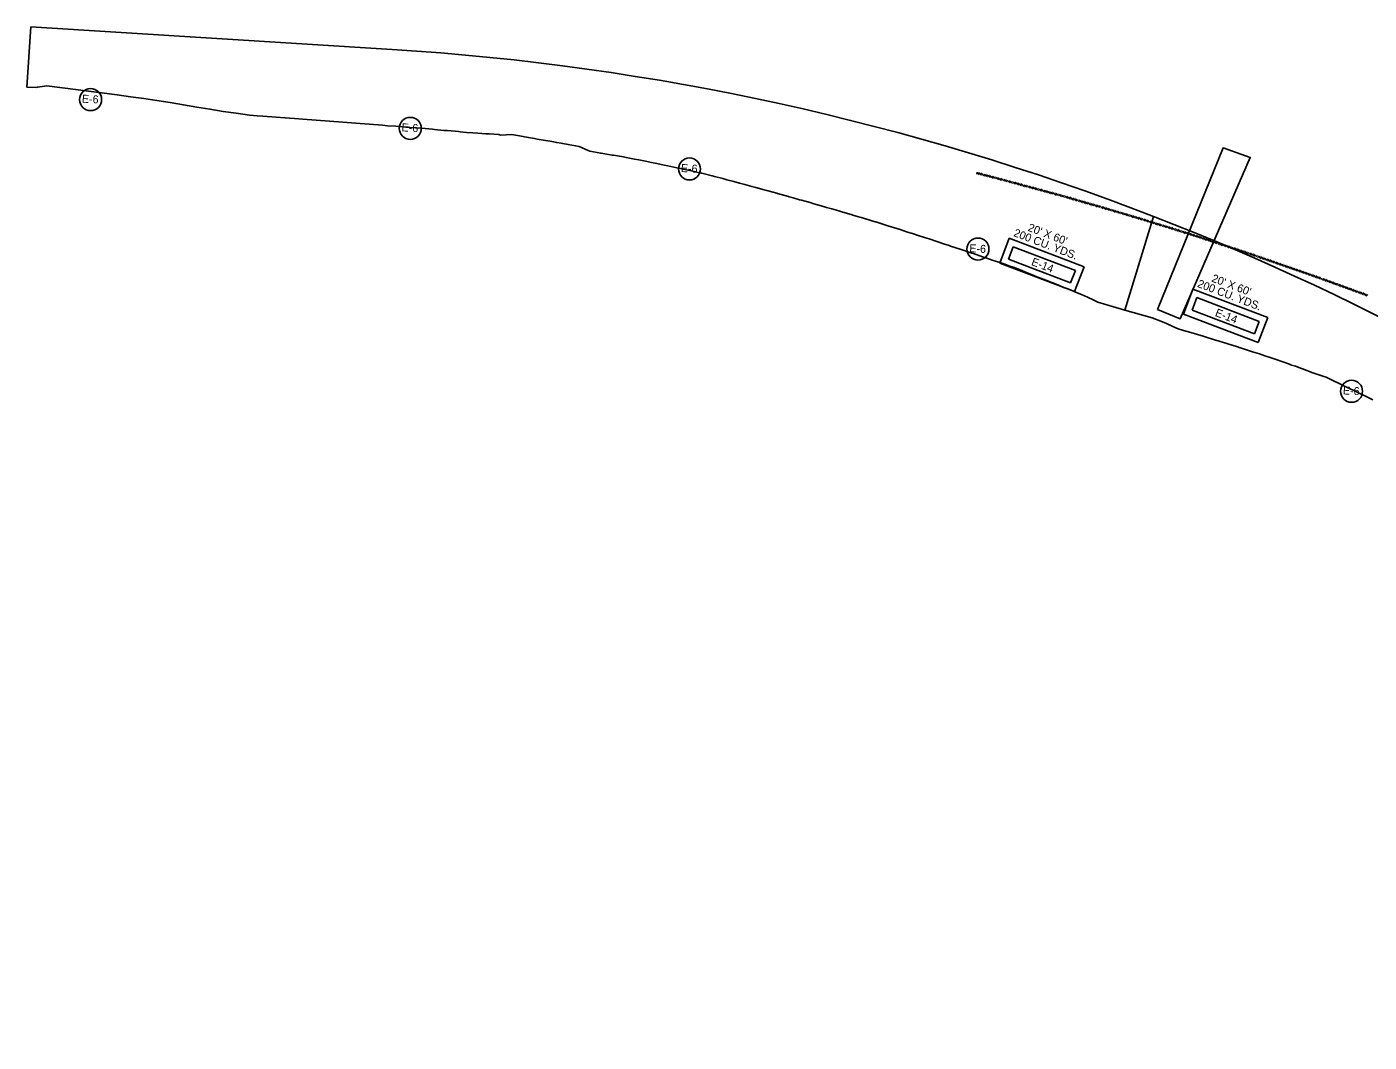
# Model space of a CAD drawing. Extents: x 881727 to 890277, y 1562105 to 1567179.
# Drawn here: x 881727 to 882733, y 1566418 to 1567179 of the extents above; entities that cross this region are included whole.
import ezdxf

# ---------------------------------------------------------------- set-up
doc = ezdxf.new("R2010")
doc.units = 0
for name, color, linetype in [('22', 7, 'Continuous'), ('R_Axis', 7, 'Continuous'), ('R_Water', 7, 'Continuous')]:
    doc.layers.add(name, color=color, linetype=linetype)

msp = doc.modelspace()

# ---------------------------------------------------------------- linework, layer by layer
at = {"layer": '22'}
for p, q in [((881729.8, 1567178.9), (881726.9, 1567133.7)), ((882000.8, 1567162), (881729.8, 1567178.9)), ((882550.2, 1566966.6), (882571.8, 1567036.8)), ((882550.2, 1566966.6), (882571.8, 1567036.8)), ((882550.2, 1566966.6), (882550.2, 1566966.6)), ((882550.3, 1566966.6), (882550.2, 1566966.6))]:
    msp.add_line(p, q, dxfattribs=at)
for points in [[(881726.9, 1567133.7), (881733.8, 1567133.4), (881734.9, 1567133.7), (881741.8, 1567134.7)], [(881741.8, 1567134.7), (881784.8, 1567129.2), (881794.7, 1567127.9), (881804.6, 1567126.5), (881814.6, 1567125.3), (881824.5, 1567123.7), (881834.4, 1567122.1), (881844.3, 1567120.4), (881854.3, 1567118.8), (881864.2, 1567117.2), (881874.1, 1567115.5), (881884, 1567114.1), (881894, 1567112.8), (881899.6, 1567112.3), (881903.9, 1567112), (881913.9, 1567111.2), (881923.9, 1567110.4), (881927.7, 1567110.1), (881933.8, 1567109.6), (881943.8, 1567108.9), (881953.8, 1567108.1), (881963.8, 1567107.4), (881973.7, 1567106.6), (881983.7, 1567105.9), (881993.7, 1567105.1), (881997.3, 1567104.8), (882003.5, 1567104.4), (882005.8, 1567104.2), (882011.1, 1567103.8), (882013.1, 1567103.6), (882014.2, 1567103.5), (882022.7, 1567102.9), (882022.8, 1567102.9), (882031.2, 1567102.1), (882032.5, 1567102), (882039.7, 1567101.3), (882042.1, 1567101.2), (882048.2, 1567100.7), (882050.5, 1567100.5), (882051.8, 1567100.3), (882056.6, 1567099.8), (882061.4, 1567099.4), (882065.1, 1567099.1), (882071.1, 1567098.7), (882073.6, 1567098.6), (882080.8, 1567098.1), (882082.1, 1567097.8), (882090.6, 1567098.1), (882090.7, 1567098.1), (882099.1, 1567096.6), (882100.1, 1567096.4), (882107.5, 1567095.2), (882109.7, 1567094.8), (882115.9, 1567093.7), (882119.3, 1567093.1), (882124.3, 1567092.2), (882127.5, 1567091.7), (882128.8, 1567091.4), (882132.7, 1567090.8), (882138.4, 1567089.8), (882141, 1567089.3), (882147.7, 1567086.3), (882149.1, 1567085.7), (882157.2, 1567084.2), (882157.5, 1567084.2), (882165.9, 1567082.8), (882166.7, 1567082.7), (882174.2, 1567081.4), (882176.3, 1567081), (882182.6, 1567079.8), (882185.8, 1567079.2), (882190.9, 1567078.2), (882195.3, 1567077.3), (882199.2, 1567076.5), (882204.8, 1567075.3), (882207.6, 1567074.7), (882214.2, 1567073.3), (882215.9, 1567073), (882223.7, 1567071.3), (882224.2, 1567071.2), (882232.4, 1567069.3), (882233.1, 1567069.1), (882240.7, 1567067.2), (882242.5, 1567066.7), (882248.9, 1567065.1), (882251.9, 1567064.3), (882257.1, 1567062.9), (882261.2, 1567061.8), (882265.3, 1567060.7), (882270.6, 1567059.3), (882273.5, 1567058.5), (882279.9, 1567056.7), (882281.7, 1567056.2), (882289.2, 1567054.1), (882289.9, 1567053.9), (882298, 1567051.6), (882298.5, 1567051.4), (882301.6, 1567050.6), (882306.2, 1567049.3), (882307.8, 1567048.9), (882314.3, 1567047.1), (882317.1, 1567046.3), (882322.5, 1567044.8), (882326.4, 1567043.6), (882330.6, 1567042.4), (882335.7, 1567041), (882338.8, 1567040.1), (882344.9, 1567038.2), (882346.9, 1567037.6), (882354.2, 1567035.5), (882355, 1567035.2), (882363.1, 1567032.8), (882363.4, 1567032.7), (882371.1, 1567030.2), (882372.6, 1567029.8), (882379.2, 1567027.7), (882381.8, 1567026.9), (882387.3, 1567025.1), (882391, 1567023.9), (882395.3, 1567022.5), (882400.1, 1567020.9), (882403.4, 1567019.9), (882409.3, 1567018), (882411.4, 1567017.3), (882414.2, 1567016.3), (882418.4, 1567014.9), (882419.4, 1567014.6), (882427.5, 1567012), (882427.6, 1567011.9), (882435.5, 1567009.3), (882436.7, 1567008.9), (882443.5, 1567006.6), (882445.9, 1567005.8), (882451.5, 1567003.8), (882455, 1567002.7), (882459.5, 1567001.2), (882464.1, 1566999.6), (882467.4, 1566998.4), (882473.1, 1566996.2), (882475.3, 1566995.3), (882480.2, 1566993.3), (882482, 1566992.6), (882483.1, 1566992.1), (882491, 1566989.1), (882491, 1566989.1), (882498.8, 1566985.9), (882499.9, 1566985.4), (882504.3, 1566983.6), (882506.7, 1566982.7), (882508.8, 1566981.9), (882514.5, 1566979.6), (882517.7, 1566978.2), (882522.3, 1566976.2), (882526.5, 1566974.3), (882529.9, 1566972.5), (882550.2, 1566966.6)], [(882570.7, 1566960.7), (882550.3, 1566966.6)], [(882736.1, 1566899.3), (882730.2, 1566902.2), (882727.4, 1566903.6), (882722.5, 1566906), (882718.6, 1566907.8), (882714.9, 1566909.6), (882709.9, 1566912), (882707.2, 1566913.3), (882701.1, 1566916.2), (882699.4, 1566916.8), (882691.9, 1566919.4), (882691.3, 1566919.6), (882683.4, 1566922.6), (882682.8, 1566922.8), (882678.2, 1566924.5), (882675.3, 1566925.4), (882673.6, 1566926), (882669.5, 1566927.5), (882667.3, 1566928.3), (882664.5, 1566929.3), (882659.2, 1566931.1), (882655.2, 1566932.3), (882651.1, 1566933.7), (882645.9, 1566935.3), (882642.9, 1566936.3), (882636.9, 1566938.3), (882636.7, 1566938.3), (882634.8, 1566938.9), (882627.4, 1566941.2), (882626.7, 1566941.4), (882618.5, 1566944), (882618.2, 1566944.1), (882610.4, 1566946.4), (882608.9, 1566946.9), (882602.3, 1566948.9), (882599.6, 1566949.7), (882594.1, 1566951.3), (882590.3, 1566952.5), (882586.2, 1566954.3), (882581.5, 1566956.4), (882578.5, 1566957.7), (882570.7, 1566960.7)]]:
    msp.add_lwpolyline(points, dxfattribs=at)
msp.add_lwpolyline([(882574.6, 1566967), (882623.9, 1567088.1), (882644.2, 1567081), (882591.8, 1566960.1)], close=True, dxfattribs=at)
for start, end in [(68.8256, 86.4305), (37.4722, 68.8256)]:
    msp.add_arc((881881.9, 1565255.8), 1909.9, start, end, dxfattribs=at)
at = {"layer": 'R_Water'}
for p, q in [((882439.2, 1567068.5), (882439.6, 1567069.9)), ((882439.2, 1567068.5), (882440.5, 1567069.7)), ((882440.3, 1567068.2), (882441.7, 1567069.4)), ((882441.5, 1567067.9), (882442.9, 1567069.1)), ((882442.7, 1567067.6), (882444, 1567068.8)), ((882443.9, 1567067.3), (882445.2, 1567068.5)), ((882445, 1567067), (882446.4, 1567068.2)), ((882446.2, 1567066.7), (882447.5, 1567067.9)), ((882447.3, 1567066.4), (882448.7, 1567067.6)), ((882448.5, 1567066.1), (882449.9, 1567067.3)), ((882449.7, 1567065.8), (882451, 1567067)), ((882450.8, 1567065.5), (882452.2, 1567066.7)), ((882452, 1567065.2), (882453.3, 1567066.4)), ((882453.2, 1567064.9), (882454.5, 1567066.1)), ((882454.3, 1567064.6), (882455.7, 1567065.8)), ((882455.5, 1567064.3), (882456.8, 1567065.5)), ((882456.6, 1567064), (882458, 1567065.2)), ((882457.8, 1567063.7), (882459.1, 1567064.9)), ((882459, 1567063.4), (882460.3, 1567064.6)), ((882460.1, 1567063.1), (882461.5, 1567064.3)), ((882461.3, 1567062.8), (882462.6, 1567064)), ((882462.4, 1567062.5), (882463.8, 1567063.7)), ((882463.6, 1567062.1), (882464.9, 1567063.3)), ((882464.7, 1567061.8), (882466.1, 1567063)), ((882465.9, 1567061.5), (882467.2, 1567062.7)), ((882467, 1567061.2), (882468.4, 1567062.4)), ((882468.2, 1567060.9), (882469.5, 1567062.1)), ((882469.3, 1567060.6), (882470.7, 1567061.8)), ((882470.5, 1567060.3), (882471.8, 1567061.5)), ((882471.6, 1567060), (882473, 1567061.2)), ((882472.8, 1567059.7), (882474.1, 1567060.8)), ((882473.9, 1567059.3), (882475.3, 1567060.5)), ((882475.1, 1567059), (882476.4, 1567060.2)), ((882476.2, 1567058.7), (882477.6, 1567059.9)), ((882477.4, 1567058.4), (882478.7, 1567059.6)), ((882478.5, 1567058.1), (882479.9, 1567059.3)), ((882479.7, 1567057.8), (882481, 1567059)), ((882480.8, 1567057.5), (882482.2, 1567058.7)), ((882482, 1567057.2), (882483.3, 1567058.4)), ((882483.1, 1567056.9), (882484.5, 1567058)), ((882484.3, 1567056.5), (882485.6, 1567057.7)), ((882485.4, 1567056.2), (882486.8, 1567057.4)), ((882486.6, 1567055.9), (882487.9, 1567057.1)), ((882487.7, 1567055.6), (882489.1, 1567056.8)), ((882488.9, 1567055.3), (882490.2, 1567056.5)), ((882490, 1567055), (882491.4, 1567056.2)), ((882491.2, 1567054.7), (882492.5, 1567055.9)), ((882492.3, 1567054.4), (882493.7, 1567055.5)), ((882493.5, 1567054), (882494.8, 1567055.2)), ((882494.6, 1567053.7), (882496, 1567054.9)), ((882495.8, 1567053.4), (882497.1, 1567054.6)), ((882496.9, 1567053.1), (882498.3, 1567054.3)), ((882498.1, 1567052.8), (882499.4, 1567054)), ((882499.2, 1567052.5), (882500.6, 1567053.7)), ((882500.4, 1567052.2), (882501.7, 1567053.4)), ((882501.5, 1567051.9), (882502.8, 1567053)), ((882502.7, 1567051.5), (882504, 1567052.7)), ((882503.8, 1567051.2), (882505.1, 1567052.4)), ((882504.9, 1567050.9), (882506.2, 1567052.1)), ((882506.1, 1567050.6), (882507.4, 1567051.7)), ((882507.2, 1567050.2), (882508.5, 1567051.4)), ((882508.3, 1567049.9), (882509.7, 1567051.1)), ((882509.5, 1567049.6), (882510.8, 1567050.8)), ((882510.6, 1567049.3), (882511.9, 1567050.4)), ((882511.7, 1567048.9), (882513.1, 1567050.1)), ((882512.9, 1567048.6), (882514.2, 1567049.8)), ((882514, 1567048.3), (882515.3, 1567049.5)), ((882515.1, 1567047.9), (882516.5, 1567049.1)), ((882516.3, 1567047.6), (882517.6, 1567048.8)), ((882517.4, 1567047.3), (882518.7, 1567048.5)), ((882518.5, 1567047), (882519.9, 1567048.1)), ((882519.7, 1567046.6), (882521, 1567047.8)), ((882520.8, 1567046.3), (882522.1, 1567047.5)), ((882521.9, 1567046), (882523.3, 1567047.2)), ((882523.1, 1567045.7), (882524.4, 1567046.8)), ((882524.2, 1567045.3), (882525.5, 1567046.5)), ((882525.3, 1567045), (882526.7, 1567046.2)), ((882526.5, 1567044.7), (882527.8, 1567045.9)), ((882527.6, 1567044.4), (882528.9, 1567045.5)), ((882528.7, 1567044), (882530.1, 1567045.2)), ((882529.9, 1567043.7), (882531.2, 1567044.9)), ((882531, 1567043.4), (882532.3, 1567044.6)), ((882532.1, 1567043), (882533.5, 1567044.2)), ((882533.3, 1567042.7), (882534.6, 1567043.9)), ((882534.4, 1567042.4), (882535.7, 1567043.6)), ((882535.5, 1567042.1), (882536.9, 1567043.3)), ((882536.7, 1567041.7), (882538, 1567042.9)), ((882537.8, 1567041.4), (882539.1, 1567042.6)), ((882538.9, 1567041.1), (882540.3, 1567042.3)), ((882540.1, 1567040.8), (882541.4, 1567041.9)), ((882541.2, 1567040.4), (882542.5, 1567041.6)), ((882542.3, 1567040.1), (882543.7, 1567041.3)), ((882543.5, 1567039.8), (882544.8, 1567041)), ((882544.6, 1567039.5), (882545.9, 1567040.6)), ((882545.7, 1567039.1), (882547, 1567040.3)), ((882546.9, 1567038.8), (882548.2, 1567040)), ((882548, 1567038.4), (882549.3, 1567039.6)), ((882549.1, 1567038.1), (882550.4, 1567039.3)), ((882550.2, 1567037.8), (882551.5, 1567038.9)), ((882551.3, 1567037.4), (882552.6, 1567038.6)), ((882552.5, 1567037.1), (882553.8, 1567038.3)), ((882553.6, 1567036.8), (882554.9, 1567037.9)), ((882554.7, 1567036.4), (882556, 1567037.6)), ((882555.8, 1567036.1), (882557.1, 1567037.3)), ((882556.9, 1567035.7), (882558.3, 1567036.9)), ((882558.1, 1567035.4), (882559.4, 1567036.6)), ((882559.2, 1567035.1), (882560.5, 1567036.2)), ((882560.3, 1567034.7), (882561.6, 1567035.9)), ((882561.4, 1567034.4), (882562.7, 1567035.5)), ((882562.5, 1567034), (882563.8, 1567035.2)), ((882563.6, 1567033.7), (882565, 1567034.9)), ((882564.8, 1567033.4), (882566.1, 1567034.5)), ((882565.9, 1567033), (882567.2, 1567034.2)), ((882567, 1567032.7), (882568.3, 1567033.8)), ((882568.1, 1567032.3), (882569.4, 1567033.5)), ((882569.2, 1567032), (882570.5, 1567033.1)), ((882570.3, 1567031.6), (882571.6, 1567032.8)), ((882571.5, 1567031.3), (882572.8, 1567032.5)), ((882572.6, 1567031), (882573.9, 1567032.1)), ((882573.7, 1567030.6), (882575, 1567031.8)), ((882574.8, 1567030.3), (882576.1, 1567031.4)), ((882575.9, 1567029.9), (882577.2, 1567031.1)), ((882577, 1567029.6), (882578.3, 1567030.7)), ((882578.2, 1567029.2), (882579.5, 1567030.4)), ((882579.3, 1567028.9), (882580.6, 1567030.1)), ((882456.4, 1567001.8), (882463.5, 1567020.5)), ((882463.5, 1567020.5), (882519.6, 1566999.1)), ((882580.4, 1567028.6), (882581.7, 1567029.7)), ((882581.5, 1567028.2), (882582.8, 1567029.4)), ((882582.6, 1567027.9), (882583.9, 1567029)), ((882583.7, 1567027.5), (882585, 1567028.7)), ((882584.8, 1567027.2), (882586.1, 1567028.4)), ((882586, 1567026.8), (882587.3, 1567028)), ((882587.1, 1567026.5), (882588.4, 1567027.7)), ((882588.2, 1567026.1), (882589.5, 1567027.3)), ((882589.3, 1567025.8), (882590.6, 1567027)), ((882590.4, 1567025.5), (882591.7, 1567026.6)), ((882591.5, 1567025.1), (882592.8, 1567026.3)), ((882592.6, 1567024.8), (882593.9, 1567025.9)), ((882593.7, 1567024.4), (882595, 1567025.6)), ((882594.8, 1567024.1), (882596.1, 1567025.2)), ((882595.9, 1567023.7), (882597.2, 1567024.9)), ((882597.1, 1567023.4), (882598.4, 1567024.5)), ((882598.2, 1567023), (882599.5, 1567024.2)), ((882599.3, 1567022.7), (882600.6, 1567023.8)), ((882600.4, 1567022.3), (882601.7, 1567023.5)), ((882601.5, 1567022), (882602.8, 1567023.1)), ((882602.6, 1567021.6), (882603.9, 1567022.8)), ((882603.7, 1567021.2), (882605, 1567022.4)), ((882604.8, 1567020.9), (882606.1, 1567022)), ((882605.9, 1567020.5), (882607.2, 1567021.7)), ((882607, 1567020.2), (882608.3, 1567021.3)), ((882608.1, 1567019.8), (882609.4, 1567021)), ((882609.2, 1567019.4), (882610.5, 1567020.6)), ((882610.3, 1567019.1), (882611.6, 1567020.2)), ((882462.9, 1567004.7), (882466.4, 1567014)), ((882466.4, 1567014), (882513.2, 1566996.2)), ((882611.4, 1567018.7), (882612.6, 1567019.9)), ((882612.5, 1567018.4), (882613.7, 1567019.5)), ((882613.6, 1567018), (882614.8, 1567019.2)), ((882614.6, 1567017.6), (882615.9, 1567018.8)), ((882615.7, 1567017.3), (882617, 1567018.4)), ((882616.8, 1567016.9), (882618.1, 1567018.1)), ((882617.9, 1567016.6), (882619.2, 1567017.7)), ((882619, 1567016.2), (882620.3, 1567017.4)), ((882620.1, 1567015.8), (882621.4, 1567017)), ((882621.2, 1567015.5), (882622.5, 1567016.6)), ((882622.3, 1567015.1), (882623.6, 1567016.3)), ((882623.4, 1567014.8), (882624.7, 1567015.9)), ((882624.5, 1567014.4), (882625.8, 1567015.6)), ((882625.6, 1567014), (882626.9, 1567015.2)), ((882626.7, 1567013.7), (882628, 1567014.8)), ((882627.8, 1567013.3), (882629.1, 1567014.5)), ((882628.9, 1567013), (882630.2, 1567014.1)), ((882630, 1567012.6), (882631.3, 1567013.8)), ((882631.1, 1567012.2), (882632.4, 1567013.4)), ((882632.2, 1567011.9), (882633.5, 1567013)), ((882633.3, 1567011.5), (882634.6, 1567012.7)), ((882634.4, 1567011.2), (882635.7, 1567012.3)), ((882635.5, 1567010.8), (882636.8, 1567012)), ((882636.6, 1567010.4), (882637.9, 1567011.6)), ((882637.7, 1567010.1), (882639, 1567011.2)), ((882638.8, 1567009.7), (882640, 1567010.9)), ((882639.9, 1567009.4), (882641.1, 1567010.5)), ((882641, 1567009), (882642.2, 1567010.1)), ((882512.5, 1566980.4), (882456.4, 1567001.8)), ((882509.6, 1566986.9), (882462.9, 1567004.7)), ((882642, 1567008.6), (882643.3, 1567009.8)), ((882643.1, 1567008.3), (882644.4, 1567009.4)), ((882644.2, 1567007.9), (882645.5, 1567009.1)), ((882645.3, 1567007.5), (882646.6, 1567008.7)), ((882646.4, 1567007.2), (882647.7, 1567008.3)), ((882647.5, 1567006.8), (882648.8, 1567007.9)), ((882648.6, 1567006.4), (882649.8, 1567007.6)), ((882649.6, 1567006), (882650.9, 1567007.2)), ((882650.7, 1567005.7), (882652, 1567006.8)), ((882651.8, 1567005.3), (882653.1, 1567006.4)), ((882652.9, 1567004.9), (882654.2, 1567006.1)), ((882654, 1567004.5), (882655.2, 1567005.7)), ((882655, 1567004.2), (882656.3, 1567005.3)), ((882656.1, 1567003.8), (882657.4, 1567004.9)), ((882657.2, 1567003.4), (882658.5, 1567004.6)), ((882658.3, 1567003), (882659.6, 1567004.2)), ((882659.4, 1567002.7), (882660.6, 1567003.8)), ((882660.4, 1567002.3), (882661.7, 1567003.4)), ((882661.5, 1567001.9), (882662.8, 1567003.1)), ((882662.6, 1567001.5), (882663.9, 1567002.7)), ((882663.7, 1567001.2), (882665, 1567002.3)), ((882664.8, 1567000.8), (882666, 1567001.9)), ((882665.8, 1567000.4), (882667.1, 1567001.6)), ((882666.9, 1567000.1), (882668.2, 1567001.2)), ((882668, 1566999.7), (882669.3, 1567000.8)), ((882669.1, 1566999.3), (882670.4, 1567000.4)), ((882670.2, 1566998.9), (882671.4, 1567000.1)), ((882513.2, 1566996.2), (882509.6, 1566986.9)), ((882519.6, 1566999.1), (882512.5, 1566980.4)), ((882671.2, 1566998.6), (882672.5, 1566999.7)), ((882672.3, 1566998.2), (882673.6, 1566999.3)), ((882673.4, 1566997.8), (882674.7, 1566999)), ((882674.5, 1566997.4), (882675.8, 1566998.6)), ((882675.6, 1566997.1), (882676.8, 1566998.2)), ((882676.7, 1566996.7), (882677.9, 1566997.8)), ((882677.7, 1566996.3), (882679, 1566997.5)), ((882678.8, 1566995.9), (882680.1, 1566997.1)), ((882679.9, 1566995.6), (882681.2, 1566996.7)), ((882681, 1566995.2), (882682.2, 1566996.3)), ((882682.1, 1566994.8), (882683.3, 1566996)), ((882683.1, 1566994.4), (882684.4, 1566995.6)), ((882684.2, 1566994.1), (882685.5, 1566995.2)), ((882685.3, 1566993.7), (882686.6, 1566994.8)), ((882686.4, 1566993.3), (882687.6, 1566994.5)), ((882687.4, 1566992.9), (882688.7, 1566994.1)), ((882688.5, 1566992.5), (882689.8, 1566993.7)), ((882689.6, 1566992.2), (882690.9, 1566993.3)), ((882690.7, 1566991.8), (882691.9, 1566992.9)), ((882691.7, 1566991.4), (882693, 1566992.5)), ((882692.8, 1566991), (882694.1, 1566992.2)), ((882693.9, 1566990.6), (882695.1, 1566991.8)), ((882694.9, 1566990.2), (882696.2, 1566991.4)), ((882696, 1566989.9), (882697.3, 1566991)), ((882697.1, 1566989.5), (882698.3, 1566990.6)), ((882698.1, 1566989.1), (882699.4, 1566990.2)), ((882699.2, 1566988.7), (882700.5, 1566989.9)), ((882594.2, 1566963.6), (882601.3, 1566982.3)), ((882601.3, 1566982.3), (882657.4, 1566961)), ((882700.3, 1566988.3), (882701.6, 1566989.5)), ((882701.4, 1566987.9), (882702.6, 1566989.1)), ((882702.4, 1566987.6), (882703.7, 1566988.7)), ((882703.5, 1566987.2), (882704.8, 1566988.3)), ((882704.6, 1566986.8), (882705.8, 1566987.9)), ((882705.6, 1566986.4), (882706.9, 1566987.5)), ((882706.7, 1566986), (882708, 1566987.1)), ((882707.8, 1566985.6), (882709, 1566986.8)), ((882708.8, 1566985.2), (882710.1, 1566986.4)), ((882709.9, 1566984.8), (882711.1, 1566986)), ((882710.9, 1566984.5), (882712.2, 1566985.6)), ((882712, 1566984.1), (882713.3, 1566985.2)), ((882713.1, 1566983.7), (882714.3, 1566984.8)), ((882714.1, 1566983.3), (882715.4, 1566984.4)), ((882715.2, 1566982.9), (882716.5, 1566984)), ((882716.3, 1566982.5), (882717.5, 1566983.7)), ((882717.3, 1566982.1), (882718.6, 1566983.3)), ((882718.4, 1566981.7), (882719.7, 1566982.9)), ((882719.5, 1566981.4), (882720.7, 1566982.5)), ((882720.5, 1566981), (882721.8, 1566982.1)), ((882721.6, 1566980.6), (882722.9, 1566981.7)), ((882722.7, 1566980.2), (882723.9, 1566981.3)), ((882723.7, 1566979.8), (882725, 1566980.9)), ((882724.8, 1566979.4), (882726.1, 1566980.6)), ((882725.9, 1566979), (882727.1, 1566980.2)), ((882726.9, 1566978.7), (882728.2, 1566979.8)), ((882600.7, 1566966.5), (882604.2, 1566975.9)), ((882604.2, 1566975.9), (882650.9, 1566958.1)), ((882728, 1566978.3), (882729.3, 1566979.4)), ((882729.1, 1566977.9), (882730.3, 1566979)), ((882730.1, 1566977.5), (882731.4, 1566978.6)), ((882731.2, 1566977.1), (882732.5, 1566978.2)), ((882650.3, 1566942.3), (882594.2, 1566963.6)), ((882647.4, 1566948.7), (882600.7, 1566966.5)), ((882657.4, 1566961), (882650.3, 1566942.3)), ((882650.9, 1566958.1), (882647.4, 1566948.7))]:
    msp.add_line(p, q, dxfattribs=at)
for centre in [(881774.7, 1567124.4), (882014.4, 1567102.8), (882223.8, 1567072.4), (882440.1, 1567012.3), (882720.2, 1566905.7)]:
    msp.add_circle(centre, 8.26, dxfattribs=at)

# ---------------------------------------------------------------- texts
at = {"layer": 'R_Axis'}
for s, rotation, p in [("20' X 60'", 339.1446, (882477, 1567026.2)), ('200 CU. YDS. ', 339.1446, (882466.3, 1567022.2)), ('E-14', 339.133, (882479.6, 1567000.5)), ("20' X 60'", 339.1446, (882614.8, 1566988.1)), ('200 CU. YDS. ', 339.1446, (882604.1, 1566984.1)), ('E-14', 339.133, (882617.4, 1566962.3))]:
    msp.add_text(s, height=6, rotation=rotation, dxfattribs=at).set_placement(p)
at = {"layer": 'R_Water'}
for p in [(881768.1, 1567122.1), (882007.8, 1567100.6), (882217.2, 1567070.1), (882433.5, 1567010), (882713.6, 1566903.4)]:
    msp.add_text('E-6 ', height=6, rotation=357.1015, dxfattribs=at).set_placement(p)

doc.saveas('drawing.dxf')
